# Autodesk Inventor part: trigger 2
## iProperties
Created: 2006-04
Part Number: trigger 2
Document SubType Name: Modeling
Designer: Калинин
Author: Калинин
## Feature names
1. Выдавливание1 [Extrusion]
2. Выдавливание2 [Extrusion]
3. Выдавливание3 [Extrusion]
4. Выдавливание4 [Extrusion]
5. Сопряжение1 [Fillet]
6. Выдавливание5 [Extrusion]
7. Выдавливание6 [Extrusion]
8. Выдавливание7 [Extrusion]
9. Выдавливание8 [Extrusion]
10. Выдавливание9 [Extrusion]
11. Сопряжение2 [Fillet]
12. Сопряжение3 [Fillet]
13. Выдавливание10 [Extrusion]
14. Сопряжение4 [Fillet]
15. Сопряжение5 [Fillet]
16. Сопряжение6 [Fillet]
17. Сопряжение7 [Fillet]
18. Сопряжение8 [Fillet]
